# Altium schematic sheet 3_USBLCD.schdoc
size 302 x 215 mm
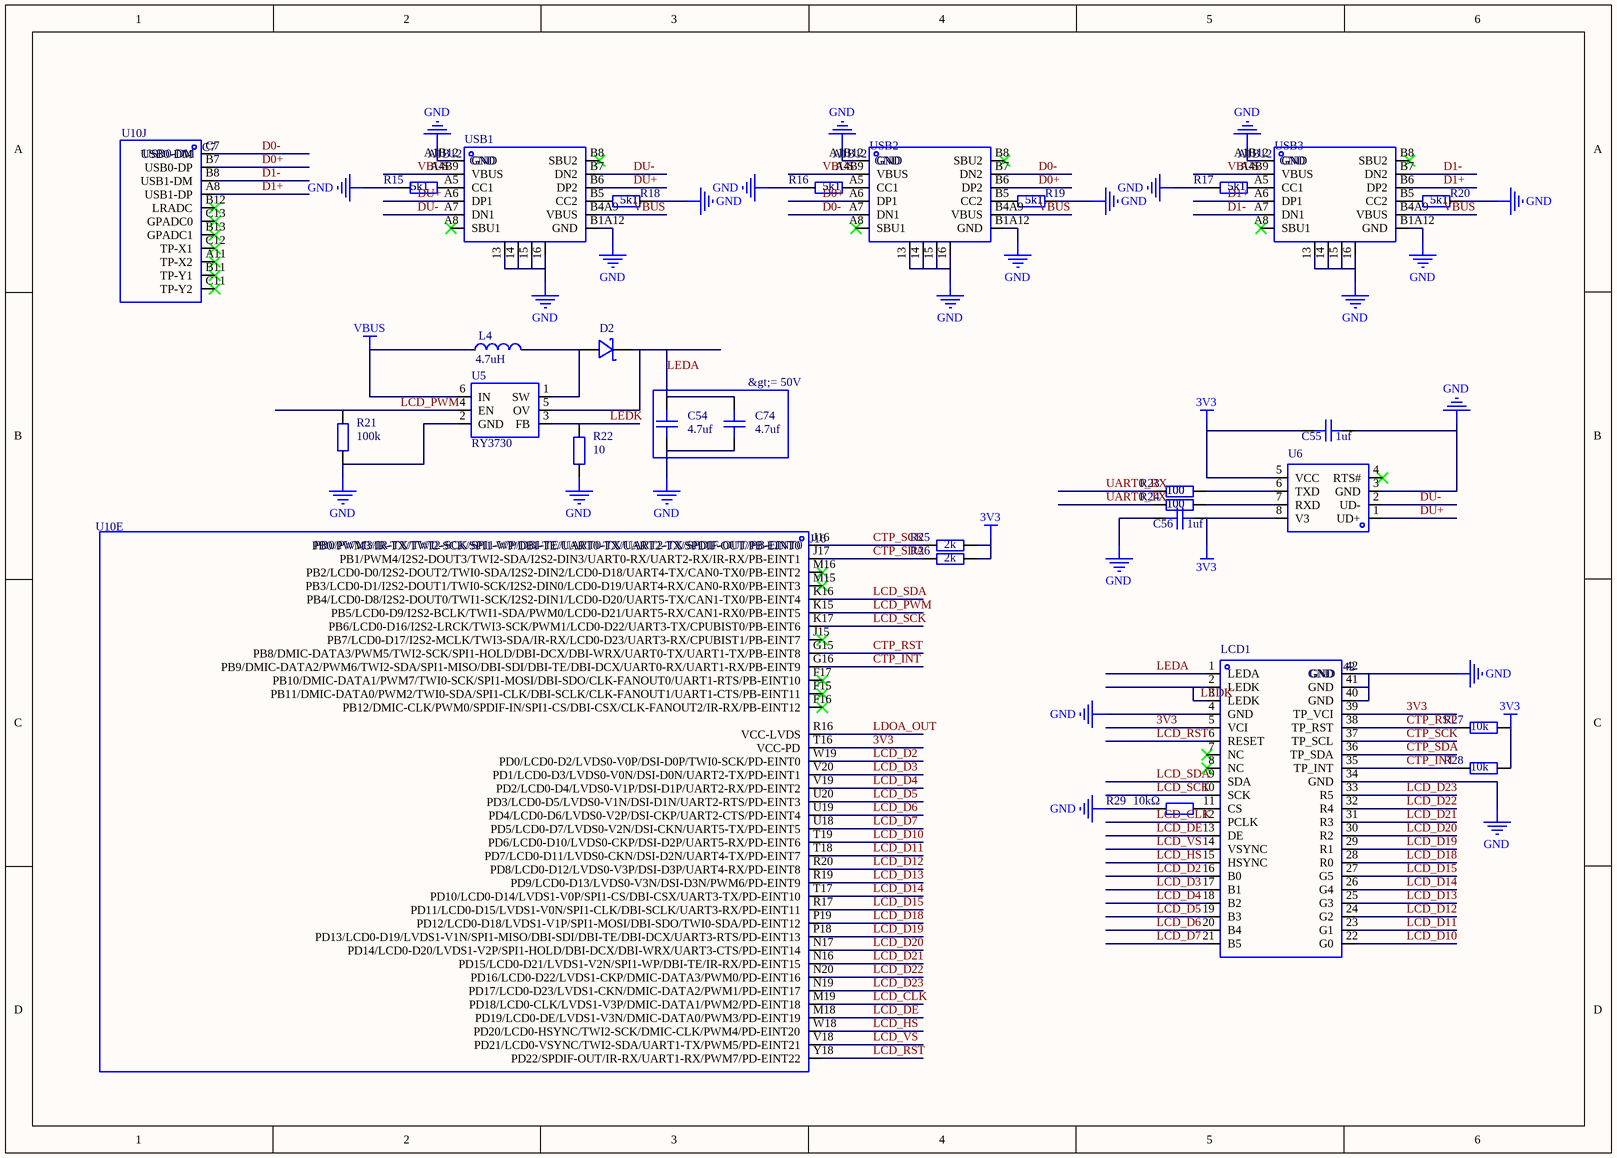
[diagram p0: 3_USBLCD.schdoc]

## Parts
C54  value 4.7uf
C55  value 1uf
C56  value 1uf
C74  value 4.7uf
D2  (no value)  [SOD-323_L1.8-W1.3-LS2.5-RD]
L4  value 4.7uH
LCD1  NAME: GND  NUMBER: 42
R15  5k1
R16  5k1
R17  5k1
R18  5k1
R19  5k1
R20  5k1
R21  value 100k
R22  value 10
R23  100
R24  100
R25  value 2k
R26  value 2k
R27  value 10k
R28  value 10k
R29  value 10kΩ
U5  value RY3730
U6  (no value)  [SOP-8_L5.0-W4.0-P1.27-LS6.0-BL]
U10  NAME: PB0/PWM3/IR-TX/TWI2-SCK/SPI1-WP/DBI-TE/UART0-TX/UART2-TX/SPDIF-OUT/PB-EINT0  NUMBER: J16  [ALLWINNER D1]  (parts E,J of 10)
USB1  NAME: GND  NUMBER: A1B12
USB2  NAME: GND  NUMBER: A1B12
USB3  NAME: GND  NUMBER: A1B12

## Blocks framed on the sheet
&gt;= 50V: C54 C74

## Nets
3V3: C55.1 C56.2 LCD1.5(VCI) LCD1.39(TP_VCI) R25.2 R26.2 R27.2 R28.2 U6.5(VCC) U6.8(V3) U10.T16(VCC-PD)
GND: C54.1 C55.2 C56.1 C74.1 LCD1.4(GND) LCD1.34(GND) LCD1.40(GND) LCD1.41(GND) LCD1.42(GND) R15.1 R16.1 R17.1 R18.2 R19.2 R20.2 R21.1 R22.1 R29.1 U5.2(GND) U6.3(GND) USB1.13 USB1.14 USB1.15 USB1.16 USB1.A1B12(GND) USB1.B1A12(GND) USB2.13 USB2.14 USB2.15 USB2.16 USB2.A1B12(GND) USB2.B1A12(GND) USB3.13 USB3.14 USB3.15 USB3.16 USB3.A1B12(GND) USB3.B1A12(GND)
VBUS: L4.1 U5.6(IN) USB1.A4B9(VBUS) USB1.B4A9(VBUS) USB2.A4B9(VBUS) USB2.B4A9(VBUS) USB3.A4B9(VBUS) USB3.B4A9(VBUS)
CTP_INT: LCD1.35(TP_INT) R28.1 U10.G16(PB9/DMIC-DATA2/PWM6/TWI2-SDA/SPI1-MISO/DBI-SDI/DBI-TE/DBI-DCX/UART0-RX/UART1-RX/PB-EINT9)
CTP_RST: LCD1.38(TP_RST) R27.1 U10.G15(PB8/DMIC-DATA3/PWM5/TWI2-SCK/SPI1-HOLD/DBI-DCX/DBI-WRX/UART0-TX/UART1-TX/PB-EINT8)
CTP_SCK: LCD1.37(TP_SCL) R25.1 U10.J16(PB0/PWM3/IR-TX/TWI2-SCK/SPI1-WP/DBI-TE/UART0-TX/UART2-TX/SPDIF-OUT/PB-EINT0)
CTP_SDA: LCD1.36(TP_SDA) R26.1 U10.J17(PB1/PWM4/I2S2-DOUT3/TWI2-SDA/I2S2-DIN3/UART0-RX/UART2-RX/IR-RX/PB-EINT1)
D0+: U10.B7(USB0-DP) USB2.A6(DP1) USB2.B6(DP2)
D0-: U10.C7(USB0-DM) USB2.A7(DN1) USB2.B7(DN2)
D1+: U10.A8(USB1-DP) USB3.A6(DP1) USB3.B6(DP2)
D1-: U10.B8(USB1-DM) USB3.A7(DN1) USB3.B7(DN2)
DU+: U6.1(UD+) USB1.A6(DP1) USB1.B6(DP2)
DU-: U6.2(UD-) USB1.A7(DN1) USB1.B7(DN2)
LCD_CLK: LCD1.12(PCLK) U10.M19(PD18/LCD0-CLK/LVDS1-V3P/DMIC-DATA1/PWM2/PD-EINT18)
LCD_D2: LCD1.16(B0) U10.W19(PD0/LCD0-D2/LVDS0-V0P/DSI-D0P/TWI0-SCK/PD-EINT0)
LCD_D3: LCD1.17(B1) U10.V20(PD1/LCD0-D3/LVDS0-V0N/DSI-D0N/UART2-TX/PD-EINT1)
LCD_D4: LCD1.18(B2) U10.V19(PD2/LCD0-D4/LVDS0-V1P/DSI-D1P/UART2-RX/PD-EINT2)
LCD_D5: LCD1.19(B3) U10.U20(PD3/LCD0-D5/LVDS0-V1N/DSI-D1N/UART2-RTS/PD-EINT3)
LCD_D6: LCD1.20(B4) U10.U19(PD4/LCD0-D6/LVDS0-V2P/DSI-CKP/UART2-CTS/PD-EINT4)
LCD_D7: LCD1.21(B5) U10.U18(PD5/LCD0-D7/LVDS0-V2N/DSI-CKN/UART5-TX/PD-EINT5)
LCD_D10: LCD1.22(G0) U10.T19(PD6/LCD0-D10/LVDS0-CKP/DSI-D2P/UART5-RX/PD-EINT6)
LCD_D11: LCD1.23(G1) U10.T18(PD7/LCD0-D11/LVDS0-CKN/DSI-D2N/UART4-TX/PD-EINT7)
LCD_D12: LCD1.24(G2) U10.R20(PD8/LCD0-D12/LVDS0-V3P/DSI-D3P/UART4-RX/PD-EINT8)
LCD_D13: LCD1.25(G3) U10.R19(PD9/LCD0-D13/LVDS0-V3N/DSI-D3N/PWM6/PD-EINT9)
LCD_D14: LCD1.26(G4) U10.T17(PD10/LCD0-D14/LVDS1-V0P/SPI1-CS/DBI-CSX/UART3-TX/PD-EINT10)
LCD_D15: LCD1.27(G5) U10.R17(PD11/LCD0-D15/LVDS1-V0N/SPI1-CLK/DBI-SCLK/UART3-RX/PD-EINT11)
LCD_D18: LCD1.28(R0) U10.P19(PD12/LCD0-D18/LVDS1-V1P/SPI1-MOSI/DBI-SDO/TWI0-SDA/PD-EINT12)
LCD_D19: LCD1.29(R1) U10.P18(PD13/LCD0-D19/LVDS1-V1N/SPI1-MISO/DBI-SDI/DBI-TE/DBI-DCX/UART3-RTS/PD-EINT13)
LCD_D20: LCD1.30(R2) U10.N17(PD14/LCD0-D20/LVDS1-V2P/SPI1-HOLD/DBI-DCX/DBI-WRX/UART3-CTS/PD-EINT14)
LCD_D21: LCD1.31(R3) U10.N16(PD15/LCD0-D21/LVDS1-V2N/SPI1-WP/DBI-TE/IR-RX/PD-EINT15)
LCD_D22: LCD1.32(R4) U10.N20(PD16/LCD0-D22/LVDS1-CKP/DMIC-DATA3/PWM0/PD-EINT16)
LCD_D23: LCD1.33(R5) U10.N19(PD17/LCD0-D23/LVDS1-CKN/DMIC-DATA2/PWM1/PD-EINT17)
LCD_DE: LCD1.13(DE) U10.M18(PD19/LCD0-DE/LVDS1-V3N/DMIC-DATA0/PWM3/PD-EINT19)
LCD_HS: LCD1.15(HSYNC) U10.W18(PD20/LCD0-HSYNC/TWI2-SCK/DMIC-CLK/PWM4/PD-EINT20)
LCD_PWM: R21.2 U5.4(EN) U10.K15(PB5/LCD0-D9/I2S2-BCLK/TWI1-SDA/PWM0/LCD0-D21/UART5-RX/CAN1-RX0/PB-EINT5)
LCD_RST: LCD1.6(RESET) U10.Y18(PD22/SPDIF-OUT/IR-RX/UART1-RX/PWM7/PD-EINT22)
LCD_SCK: LCD1.10(SCK) U10.K17(PB6/LCD0-D16/I2S2-LRCK/TWI3-SCK/PWM1/LCD0-D22/UART3-TX/CPUBIST0/PB-EINT6)
LCD_SDA: LCD1.9(SDA) U10.K16(PB4/LCD0-D8/I2S2-DOUT0/TWI1-SCK/I2S2-DIN1/LCD0-D20/UART5-TX/CAN1-TX0/PB-EINT4)
LCD_VS: LCD1.14(VSYNC) U10.V18(PD21/LCD0-VSYNC/TWI2-SDA/UART1-TX/PWM5/PD-EINT21)
LDOA_OUT: U10.R16(VCC-LVDS)
LEDA: C54.2 C74.2 D2.1(C) LCD1.1(LEDA) U5.5(OV)
LEDK: LCD1.2(LEDK) LCD1.3(LEDK) R22.2 U5.3(FB)
UART0_RX: R23.1
UART0_TX: R24.1
NetD2_2: D2.2(A) L4.2 U5.1(SW)
NetLCD1_11: LCD1.11(CS) R29.2
NetR15_2: R15.2 USB1.A5(CC1)
NetR16_2: R16.2 USB2.A5(CC1)
NetR17_2: R17.2 USB3.A5(CC1)
NetR18_1: R18.1 USB1.B5(CC2)
NetR19_1: R19.1 USB2.B5(CC2)
NetR20_1: R20.1 USB3.B5(CC2)
NetR23_2: R23.2 U6.6(TXD)
NetR24_2: R24.2 U6.7(RXD)

Not connected (* = marked no-connect by the designer): LCD1 7(NC)* 8(NC)*; U6 4(RTS#)*; U10 A11(TP-X2)* B11(TP-Y1)* B12(LRADC)* B13(GPADC1)* C11(TP-Y2)* C12(TP-X1)* C13(GPADC0)* F15(PB11/DMIC-DATA0/PWM2/TWI0-SDA/SPI1-CLK/DBI-SCLK/CLK-FANOUT1/UART1-CTS/PB-EINT11)* F16(PB12/DMIC-CLK/PWM0/SPDIF-IN/SPI1-CS/DBI-CSX/CLK-FANOUT2/IR-RX/PB-EINT12)* F17(PB10/DMIC-DATA1/PWM7/TWI0-SCK/SPI1-MOSI/DBI-SDO/CLK-FANOUT0/UART1-RTS/PB-EINT10)* J15(PB7/LCD0-D17/I2S2-MCLK/TWI3-SDA/IR-RX/LCD0-D23/UART3-RX/CPUBIST1/PB-EINT7)* M15(PB3/LCD0-D1/I2S2-DOUT1/TWI0-SCK/I2S2-DIN0/LCD0-D19/UART4-RX/CAN0-RX0/PB-EINT3)* M16(PB2/LCD0-D0/I2S2-DOUT2/TWI0-SDA/I2S2-DIN2/LCD0-D18/UART4-TX/CAN0-TX0/PB-EINT2)*; USB1 A8(SBU1)* B8(SBU2)*; USB2 A8(SBU1)* B8(SBU2)*; USB3 A8(SBU1)* B8(SBU2)*

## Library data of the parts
C54 C74 = CC0603KRX7R9BB104: Manufacturer: YAGEO(国巨); Add into BOM: yes; Tolerance: ±10%; Voltage Rated: 50V; Temperature Coefficient: X7R; Description: 容值:100nF;精度:±10%;额定电压:50V;温度系数:X7R;
C55 C56 = FN15X104K250PNG: Manufacturer: PSA(信昌电陶); Add into BOM: yes; Tolerance: ±10%; Voltage Rated: 25V; Temperature Coefficient: X7R; Description: 容值:100nF;精度:±10%;额定电压:25V;温度系数:X7R;
D2 = 1N5819WS: Manufacturer: PJSEMI(平晶微); Symbol: 1N5819WS_C440261; Add into BOM: yes; Reverse Voltage (Vr): 40V; Average Rectified Current (Io): 1A; Forward Voltage (Vf@If): 900mV@3A; Description: 直流反向耐压(Vr):40V;平均整流电流(Io):1A;正向压降(Vf):900mV@3A;
L4 = WPN252012H4R7MT: Manufacturer: Sunlord(顺络); Add into BOM: yes; Tolerance: ±20%; Rated Current: 1.25A; DC Resistance (DCR): 260m; Description: 电感值:4.7uH;精度:±20%;额定电流:1.25A;直流电阻(DCR):260m;
LCD1 = RGB TTL TP: Manufacturer: XUNPU(讯普); Manufacturer Part: FPC-05F-40PH20; Pin Type: IN; Add into BOM: yes
R15-R20 R23 R24 = R0402_2: Symbol: R0402_1; Convert to PCB: yes
R21 R22 = TR0402D10K0Q1025Z: Manufacturer: EVER OHMS(天二科技); Symbol: TR0402D10KQ1025; Add into BOM: yes; Tolerance: ±0.5%; Power(Watts): 63mW; Temperature Coefficient: ±25ppm/; Overload Voltage (Max): 25V; Description: 电阻类型:薄膜电阻;阻值:10k;精度:±0.5%;功率:63mW;温度系数:±25ppm/;最大工作电压:25V;工作温度范围:-55~+155;
R25-R29 = TR0402D10K0Q1025Z: Manufacturer: EVER OHMS(天二科技); Symbol: TR0402D10KQ1025; Add into BOM: yes; Tolerance: ±0.5%; Power(Watts): 63mW; Temperature Coefficient: ±25ppm/; Overload Voltage (Max): 25V; Description: 电阻类型:薄膜电阻;阻值:10kΩ;精度:±0.5%;功率:63mW;温度系数:±25ppm/;最大工作电压:25V;工作温度范围:-55~+155;
U5 = PT4103B23F_1: Add into BOM: yes; Description: 类型:-;拓扑结构:-;内部开关:-;供电电压（最低）:-;供电电压（最高）:-;频率:-;
U6 = CH340N: Manufacturer: WCH(南京沁恒); Add into BOM: yes
U10 = Allwinner D1-H: Pin Type: IN; Add into BOM: yes
USB1-USB3 = TYPEC-304-BCP16_3: Manufacturer: XUNPU; Symbol: TYPEC-304-BCP16_2; Pin Type: IN; Add into BOM: yes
